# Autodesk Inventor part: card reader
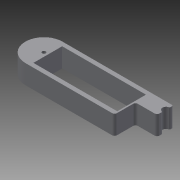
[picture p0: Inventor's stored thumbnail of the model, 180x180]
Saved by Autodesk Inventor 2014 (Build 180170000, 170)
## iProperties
Created: 2015-01
Part Number: card reader
Material: Generic
Document SubType Name: Modeling
Designer: Drano
Density: 1 g/cm^3
Appearance: Default
Author: Drano
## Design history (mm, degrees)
sketch "Sketch1"
  geometry: L1 (-37.656, 14.29)-(-37.656, -9.71); L2 (-37.656, -9.71)-(32.344, -9.71); L3 (32.344, 14.29)-(32.344, -9.71); L4 (32.344, 14.29)-(-37.656, 14.29); L5 (-40.906, -13.21)-(31.594, -13.21); L6 (-40.906, 17.79)-(36.094, 17.79); L7 (36.094, 17.79)-(50.594, 17.79); L8 (51.594, 6.29)-(51.594, 7.917); L9 (51.594, 15.663)-(51.594, 16.79); L10 (35.594, 4.29)-(49.594, 4.29); L11 (33.594, -11.21)-(33.594, 2.29); C1 r 1.5 at (-40.906, 2.29); A1 r 2 centre (31.594, -11.21) between (31.594, -13.21) and (33.594, -11.21); A2 r 15.5 centre (-40.906, 2.29) between (-40.906, 17.79) and (-40.906, -13.21); A3 r 1 centre (50.594, 16.79) between (51.594, 16.79) and (50.594, 17.79); A4 r 2 centre (49.594, 6.29) between (49.594, 4.29) and (51.594, 6.29); A5 r 3 centre (51.594, 11.79) between (50.844, 14.695) and (50.844, 8.886); A6 r 1 centre (50.594, 7.917) between (51.594, 7.917) and (50.844, 8.886); A7 r 1 centre (50.594, 15.663) between (50.844, 14.695) and (51.594, 15.663); A8 r 2 centre (35.594, 2.29) between (35.594, 4.29) and (33.594, 2.29); 1 further point
  constraints: 22 end point, 16 point on circle, 9 centre point
extrude "Extrusion1" new body sketch "Sketch1" distance "d0" = 16; taper "d1" = 0 deg
body "Solid1"
